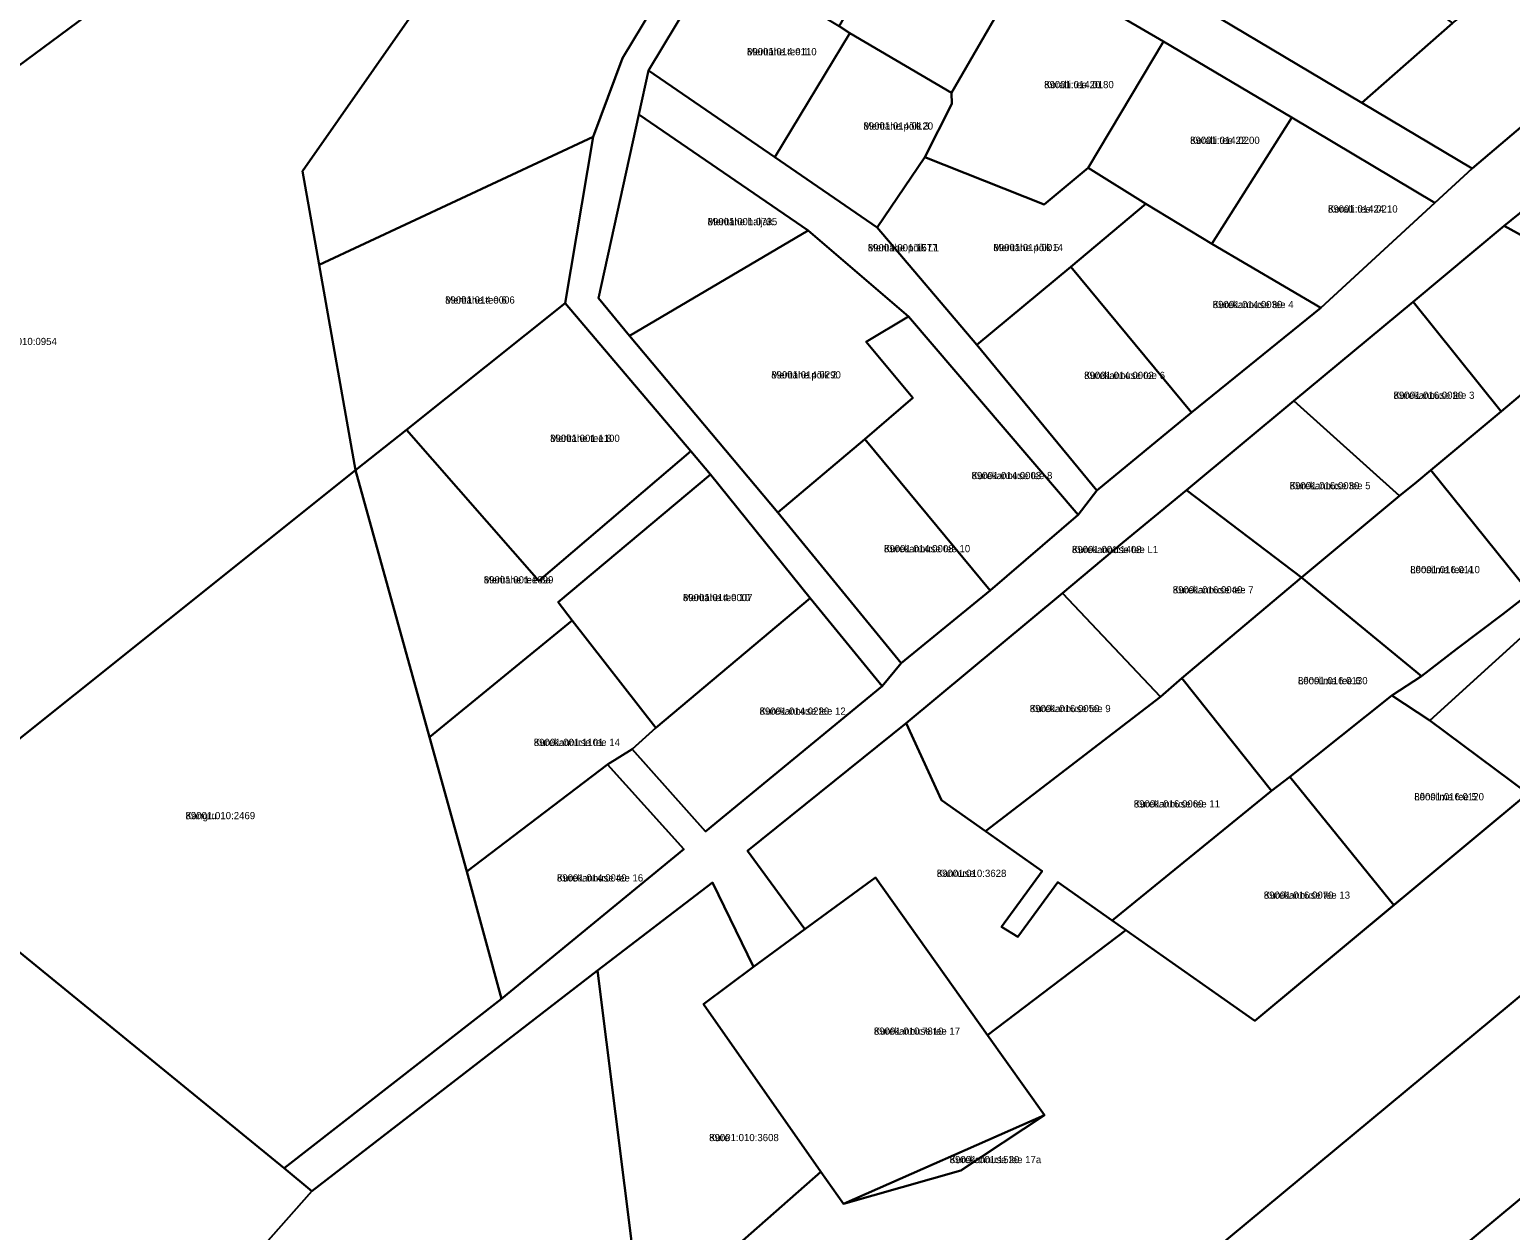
# Model space of a CAD drawing. Extents: x 526849 to 562296, y 6591741 to 6618546.
# Drawn here: x 551245.1 to 551553.4, y 6595510 to 6595760 of the extents above; entities that cross this region are included whole.
import ezdxf

# ---------------------------------------------------------------- set-up
doc = ezdxf.new("R2010")
doc.units = 0
for name, color, linetype in [('L_AADRESS', 7, 'Continuous'), ('PIIR', 7, 'Continuous'), ('TUNNUS', 7, 'Continuous')]:
    doc.layers.add(name, color=color, linetype=linetype)

msp = doc.modelspace()

# ---------------------------------------------------------------- linework, layer by layer
at = {"layer": 'PIIR'}
for points in [[(551058.09, 6595896.12), (551114.18, 6595925.24), (551184.64, 6595963.47), (551210.94, 6595958.08), (551185.91, 6595941.41), (551262.5, 6595894.21), (551265.05, 6595892.64), (551259.51, 6595874.29), (551246.54, 6595851.93), (551307.06, 6595805.38), (551304.66, 6595798.26), (551127.14, 6595666.9), (551123.94, 6595664.55), (551122.47, 6595668.32), (551104.17, 6595730.59)], [(551342.58, 6595852.37), (551374.03, 6595823.61), (551355.41, 6595797), (551382.98, 6595778.11), (551368.52, 6595754.02), (551362.37, 6595737.62), (551305.33, 6595710.96), (551301.84, 6595730.52), (551331.57, 6595773.01), (551304.66, 6595798.26), (551307.06, 6595805.38), (551320.19, 6595822.18)], [(551356.53, 6595703.04), (551362.37, 6595737.62), (551368.52, 6595754.02), (551382.98, 6595778.11), (551398.85, 6595805.25), (551404.19, 6595802.55), (551388.53, 6595775.8), (551373.9, 6595751.44), (551371.9, 6595742.29), (551363.48, 6595704.03), (551369.97, 6595696.18), (551400.83, 6595659.46), (551426.5, 6595628.07), (551422.6, 6595623.26), (551407.56, 6595641.62), (551386.81, 6595667.32), (551382.75, 6595672.17)], [(551123.94, 6595664.55), (551127.14, 6595666.9), (551304.66, 6595798.26), (551331.57, 6595773.01), (551301.84, 6595730.52), (551305.33, 6595710.96), (551312.92, 6595668.22), (551215.35, 6595590.31), (551126.85, 6595662.18)], [(551541.31, 6595761.3), (551522.45, 6595744.7), (551476.67, 6595771.97), (551492.48, 6595797.16)], [(551586.25, 6595797.14), (551597.51, 6595783.8), (551592.99, 6595779.98), (551597.19, 6595775), (551545.41, 6595731.02), (551522.45, 6595744.7), (551541.31, 6595761.3), (551558.67, 6595774.88)], [(551413.61, 6595760.69), (551429.61, 6595787.65), (551452.74, 6595774.03), (551437.02, 6595746.78), (551415.82, 6595759.21)], [(551388.53, 6595775.8), (551413.61, 6595760.69), (551415.82, 6595759.21), (551400.25, 6595733.41), (551373.9, 6595751.44)], [(551431.42, 6595733.38), (551437.09, 6595744.49), (551437.02, 6595746.78), (551452.74, 6595774.03), (551481.15, 6595757.51), (551465.48, 6595731.17), (551456.32, 6595723.53)], [(551415.82, 6595759.21), (551437.02, 6595746.78), (551437.09, 6595744.49), (551431.42, 6595733.38), (551421.5, 6595718.79), (551400.25, 6595733.41)], [(551465.48, 6595731.17), (551481.15, 6595757.51), (551507.89, 6595741.66), (551491.23, 6595715.33), (551477.49, 6595723.68)], [(551463.37, 6595658.93), (551428.03, 6595700.22), (551407.19, 6595718.16), (551371.9, 6595742.29), (551373.9, 6595751.44), (551400.25, 6595733.41), (551421.5, 6595718.79), (551442.28, 6595694.31), (551467.26, 6595664.03)], [(551363.48, 6595704.03), (551371.9, 6595742.29), (551407.19, 6595718.16), (551369.97, 6595696.18)], [(551491.23, 6595715.33), (551507.89, 6595741.66), (551537.64, 6595723.91), (551513.92, 6595702.07)], [(551312.92, 6595668.22), (551305.33, 6595710.96), (551362.37, 6595737.62), (551356.53, 6595703.04), (551323.55, 6595676.67)], [(551421.5, 6595718.79), (551431.42, 6595733.38), (551456.32, 6595723.53), (551465.48, 6595731.17), (551477.49, 6595723.68), (551461.84, 6595710.58), (551442.28, 6595694.31)], [(551477.49, 6595723.68), (551491.23, 6595715.33), (551513.92, 6595702.07), (551486.96, 6595680.28), (551461.84, 6595710.58)], [(551428.03, 6595700.22), (551419.25, 6595694.95), (551428.98, 6595683.3), (551418.98, 6595674.67), (551400.83, 6595659.46), (551369.97, 6595696.18), (551407.19, 6595718.16)], [(551551.42, 6595680.47), (551533.11, 6595703.3), (551552.05, 6595719.08), (551579.59, 6595703.99), (551558.92, 6595686.74)], [(551461.84, 6595710.58), (551486.96, 6595680.28), (551467.26, 6595664.03), (551442.28, 6595694.31)], [(551351.08, 6595645.23), (551323.55, 6595676.67), (551356.53, 6595703.04), (551382.75, 6595672.17)], [(551533.11, 6595703.3), (551551.42, 6595680.47), (551536.79, 6595668.24), (551533.79, 6595665.76), (551530.26, 6595662.88), (551508.25, 6595682.67)], [(551428.98, 6595683.3), (551419.25, 6595694.95), (551428.03, 6595700.22), (551463.37, 6595658.93), (551445.05, 6595643.23), (551418.98, 6595674.67)], [(551551.42, 6595680.47), (551558.92, 6595686.74), (551578.87, 6595662.88), (551570.04, 6595654.52), (551557.45, 6595642.61), (551536.79, 6595668.24)], [(551509.87, 6595645.89), (551485.93, 6595664.1), (551508.25, 6595682.67), (551530.26, 6595662.88)], [(551328.32, 6595612.67), (551312.92, 6595668.22), (551323.55, 6595676.67), (551351.08, 6595645.23), (551382.75, 6595672.17), (551386.81, 6595667.32), (551355.08, 6595640.74), (551358.02, 6595636.97)], [(551445.05, 6595643.23), (551426.5, 6595628.07), (551400.83, 6595659.46), (551418.98, 6595674.67)], [(551298.02, 6595522.97), (551231.53, 6595577.13), (551215.35, 6595590.31), (551312.92, 6595668.22), (551328.32, 6595612.67), (551336.08, 6595584.69), (551343.33, 6595558.23)], [(551355.08, 6595640.74), (551386.81, 6595667.32), (551407.56, 6595641.62), (551375.46, 6595614.63), (551358.03, 6595636.96)], [(551509.87, 6595645.89), (551530.26, 6595662.88), (551533.79, 6595665.76), (551536.79, 6595668.24), (551557.45, 6595642.61), (551551.77, 6595638.26), (551542.24, 6595631.03), (551534.89, 6595625.37)], [(551484.98, 6595624.97), (551480.49, 6595621.08), (551460.12, 6595642.67), (551472.63, 6595653.12), (551485.93, 6595664.1), (551509.87, 6595645.89)], [(551503.65, 6595601.47), (551484.98, 6595624.97), (551509.87, 6595645.89), (551534.89, 6595625.37), (551528.69, 6595621.35), (551507.44, 6595604.43)], [(551434.89, 6595599.52), (551427.53, 6595615.58), (551460.12, 6595642.67), (551480.49, 6595621.08), (551444.05, 6595593.08)], [(551370.48, 6595610.17), (551375.46, 6595614.63), (551407.56, 6595641.62), (551422.6, 6595623.26), (551385.8, 6595593.05)], [(551556.99, 6595600.91), (551536.63, 6595616.16), (551564.74, 6595641.69), (551581.42, 6595620.53), (551599.8, 6595597.81), (551588.32, 6595588.75), (551586.12, 6595587.01), (551562.02, 6595605.09)], [(551336.08, 6595584.69), (551328.32, 6595612.67), (551358.02, 6595636.97), (551375.46, 6595614.63), (551370.48, 6595610.17), (551365.37, 6595607)], [(551459.12, 6595582.49), (551450.81, 6595571.09), (551447.38, 6595573.2), (551455.87, 6595584.77), (551444.05, 6595593.08), (551480.49, 6595621.08), (551484.98, 6595624.97), (551503.65, 6595601.47), (551470.49, 6595574.5)], [(551536.63, 6595616.16), (551556.99, 6595600.91), (551529.09, 6595577.68), (551507.44, 6595604.43), (551528.69, 6595621.35)], [(551394.52, 6595589.02), (551427.53, 6595615.58), (551434.89, 6595599.52), (551444.05, 6595593.08), (551455.87, 6595584.77), (551447.38, 6595573.2), (551450.81, 6595571.09), (551459.12, 6595582.49), (551470.49, 6595574.5), (551473.33, 6595572.5), (551444.51, 6595550.62), (551421.2, 6595583.42), (551406.48, 6595572.68)], [(551381.26, 6595589.34), (551343.33, 6595558.23), (551336.08, 6595584.69), (551365.37, 6595607)], [(551288.1, 6595418.83), (551372.63, 6595489.52), (551409.78, 6595522.16), (551414.55, 6595515.51), (551438.97, 6595522.49), (551456.34, 6595533.96), (551444.51, 6595550.62), (551473.33, 6595572.5), (551500.18, 6595553.63), (551562.02, 6595605.09), (551587.83, 6595585.74), (551586.2, 6595584.38), (551338.19, 6595378.45)], [(551500.18, 6595553.63), (551470.49, 6595574.5), (551503.65, 6595601.47), (551507.44, 6595604.43), (551529.09, 6595577.68)], [(551587.83, 6595585.74), (551612.39, 6595568.5), (551615.21, 6595566.32), (551613, 6595564.4), (551363.96, 6595357.62), (551338.19, 6595378.45), (551586.2, 6595584.38)], [(551387.23, 6595582.4), (551395.81, 6595564.85), (551385.34, 6595557.11), (551409.78, 6595522.16), (551372.63, 6595489.52), (551363.3, 6595564.06)], [(551421.2, 6595583.42), (551444.51, 6595550.62), (551456.34, 6595533.96), (551414.55, 6595515.51), (551409.78, 6595522.16), (551385.34, 6595557.11), (551395.81, 6595564.85), (551406.48, 6595572.68)], [(551006.5, 6595337.47), (550932.54, 6595426.13), (550979.44, 6595484.55), (550982.15, 6595483.07), (551100.71, 6595418.14), (551231.53, 6595577.13), (551298.02, 6595522.97), (551303.83, 6595518.16), (551245.73, 6595452.49), (551174.82, 6595364.8), (551526.05, 6595081.12), (551528.52, 6595079.13), (551526.31, 6595078.09), (551500.54, 6595065.91), (551474.53, 6595053.58), (551446.57, 6595040.26), (551410.83, 6595023.22), (551100.27, 6595271.33), (551046.75, 6595293.27), (551044.75, 6595291.57), (551008.36, 6595335.24)], [(551615.21, 6595566.32), (551639.82, 6595547.55), (551640.61, 6595546.93), (551641.15, 6595546.5), (551639.21, 6595544.88), (551390.09, 6595336.53), (551363.96, 6595357.62), (551613, 6595564.4)], [(551288.1, 6595418.83), (551245.73, 6595452.49), (551303.83, 6595518.16), (551363.3, 6595564.06), (551372.63, 6595489.52)], [(551438.97, 6595522.49), (551414.55, 6595515.51), (551456.34, 6595533.96)]]:
    msp.add_lwpolyline(points, close=True, dxfattribs=at)
for points in [[(551556.77, 6595722.94), (551552.05, 6595719.08), (551533.11, 6595703.3), (551508.25, 6595682.67), (551485.93, 6595664.1), (551472.63, 6595653.12), (551460.12, 6595642.67), (551427.53, 6595615.58), (551394.52, 6595589.02), (551406.48, 6595572.68), (551395.81, 6595564.85), (551387.23, 6595582.4), (551363.3, 6595564.06), (551303.83, 6595518.16), (551298.02, 6595522.97), (551343.33, 6595558.23), (551381.26, 6595589.34), (551365.37, 6595607), (551370.48, 6595610.17), (551385.8, 6595593.05), (551422.6, 6595623.26), (551426.5, 6595628.07), (551445.05, 6595643.23), (551463.37, 6595658.93), (551467.26, 6595664.03), (551486.96, 6595680.28), (551513.92, 6595702.07), (551537.64, 6595723.91), (551545.41, 6595731.02), (551597.19, 6595775)], [(551476.67, 6595771.97), (551522.45, 6595744.7), (551545.41, 6595731.02), (551537.64, 6595723.91), (551507.89, 6595741.66), (551481.15, 6595757.51), (551452.74, 6595774.03)], [(551579.59, 6595703.99), (551552.05, 6595719.08), (551556.77, 6595722.94)], [(551564.74, 6595641.69), (551536.63, 6595616.16), (551528.69, 6595621.35), (551534.89, 6595625.37), (551542.24, 6595631.03), (551551.77, 6595638.26), (551557.45, 6595642.61)]]:
    msp.add_lwpolyline(points, dxfattribs=at)

# ---------------------------------------------------------------- texts
at = {"layer": 'L_AADRESS'}
for s, p in [('Meritähe tee 1', (551394.42, 6595754.61)), ('Koralli tee 20', (551456.29, 6595747.76)), ('Meritähe põik 3', (551418.67, 6595739.14)), ('Koralli tee 22', (551486.68, 6595736.16)), ('Koralli tee 24', (551515.39, 6595721.87)), ('Meritähe haljak', (551386.22, 6595719.24)), ('Meritähe põik L1', (551419.58, 6595713.8)), ('Meritähe põik 5', (551445.72, 6595713.84)), ('Meritähe tee 6', (551331.57, 6595702.92)), ('Kurekannuse tee 4', (551491.39, 6595701.98)), ('Meritähe põik 2', (551399.47, 6595687.34)), ('Kurekannuse tee 6', (551464.62, 6595687.23)), ('Kurekannuse tee 3', (551529.04, 6595683.09)), ('Meritähe tee 8', (551353.43, 6595674.13)), ('Kurekannuse tee 8', (551441.17, 6595666.38)), ('Kurekannuse tee 5', (551507.42, 6595664.28)), ('Kurekannuse tee 10', (551422.94, 6595651.16)), ('Kurekannuse tee L1', (551462.08, 6595650.98)), ('Lõosilma tee 4', (551532.52, 6595646.8)), ('Meritähe tee 8a', (551339.61, 6595644.67)), ('Meritähe tee 10', (551381.08, 6595640.98)), ('Kurekannuse tee 7', (551483.07, 6595642.59)), ('Lõosilma tee 6', (551509.14, 6595623.68)), ('Kurekannuse tee 12', (551397.03, 6595617.34)), ('Kurekannuse tee 9', (551453.3, 6595617.88)), ('Kurekannuse tee 14', (551350.02, 6595610.83)), ('Kurekannuse tee 11', (551474.96, 6595598.03)), ('Lõosilma tee 5', (551533.37, 6595599.52)), ('Kangru', (551277.51, 6595595.59)), ('Kurekannuse tee 16', (551354.85, 6595582.62)), ('Kannuse', (551433.93, 6595583.57)), ('Kurekannuse tee 13', (551502.03, 6595579.03)), ('Kurekannuse tee 17', (551420.84, 6595550.72)), ('Kure', (551386.54, 6595528.57)), ('Kurekannuse tee 17a', (551436.62, 6595523.99))]:
    msp.add_text(s, height=1.5, dxfattribs=at).set_placement(p)
at = {"layer": 'TUNNUS'}
for s, p in [('89001:014:0110', (551394.42, 6595754.61)), ('89001:014:0180', (551456.29, 6595747.76)), ('89001:014:0120', (551418.67, 6595739.14)), ('89001:014:0200', (551486.68, 6595736.16)), ('89001:014:0210', (551515.39, 6595721.87)), ('89001:001:0735', (551386.22, 6595719.24)), ('89001:001:1577', (551419.58, 6595713.8)), ('89001:014:0014', (551445.72, 6595713.84)), ('89001:014:0006', (551331.57, 6595702.92)), ('89001:014:0030', (551491.39, 6595701.98)), ('89001:010:0954', (551236.22, 6595694.29)), ('89001:014:0290', (551399.47, 6595687.34)), ('89001:014:0002', (551464.62, 6595687.23)), ('89001:016:0020', (551529.04, 6595683.09)), ('89001:001:1100', (551353.43, 6595674.13)), ('89001:014:0003', (551441.17, 6595666.38)), ('89001:016:0030', (551507.42, 6595664.28)), ('89001:014:0008', (551422.94, 6595651.16)), ('89001:001:1408', (551462.08, 6595650.98)), ('89001:016:0110', (551532.52, 6595646.8)), ('89001:001:1099', (551339.61, 6595644.67)), ('89001:014:0007', (551381.08, 6595640.98)), ('89001:016:0040', (551483.07, 6595642.59)), ('89001:016:0130', (551509.14, 6595623.68)), ('89001:014:0220', (551397.03, 6595617.34)), ('89001:016:0050', (551453.3, 6595617.88)), ('89001:001:1101', (551350.02, 6595610.83)), ('89001:016:0060', (551474.96, 6595598.03)), ('89001:016:0120', (551533.37, 6595599.52)), ('89001:010:2469', (551277.51, 6595595.59)), ('89001:014:0040', (551354.85, 6595582.62)), ('89001:010:3628', (551433.93, 6595583.57)), ('89001:016:0070', (551502.03, 6595579.03)), ('89001:010:7810', (551420.84, 6595550.72)), ('89001:010:3608', (551386.54, 6595528.57)), ('89001:001:1520', (551436.62, 6595523.99))]:
    msp.add_text(s, height=1.5, dxfattribs=at).set_placement(p)

doc.saveas('drawing.dxf')
